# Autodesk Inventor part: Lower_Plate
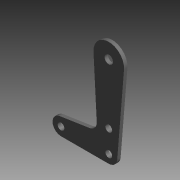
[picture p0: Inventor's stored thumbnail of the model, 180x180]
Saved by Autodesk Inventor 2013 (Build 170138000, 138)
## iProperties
Shininess: 15.0
Length Units: 11272
Angle Units: 11279
Time Units: 11290
Mass Units: 11283
Length Display Precision: 2
Angle Display Precision: 1
Compacted: True
Created: 1999-05
Part Number: Lower_Plate
Document SubType Name: Modeling
Designer: Administrator
Density: 8.83 g/cm^3
Material: NICU, Monel 400
Density: 8.83
Volumn: 8.899101648082546
Area: 68.18129680210748
PropertySet Name: Model Information
Control State: 0
Master: False
Checked Out: False
Author: Administrator
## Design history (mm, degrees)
node "y-z Plane"
  node "x-z Plane"
  node "x-y Plane"
node "Extrusion1" dims "d6" = 3.175, "d7" = 0
  sketch "Sketch1"
    geometry: L1 (-44.45, -84.074)-(0, -84.074); L2 (7.847, -76.856)-(14.175, -1.185); L3 (-14.203, -0.776)-(-11.188, -55.993); L4 (-17.87, -64.207)-(-45.63, -68.415); L5 (0, 0)-(0, -76.2); A1 r 7.874 centre (0, -76.2) between (0, -84.074) and (7.847, -76.856); A2 r 14.224 centre (0, 0) between (14.175, -1.185) and (-14.203, -0.776); A3 r 7.874 centre (-19.05, -56.422) between (-17.87, -64.207) and (-11.188, -55.993); A4 r 7.874 centre (-44.45, -76.2) between (-45.63, -68.415) and (-44.45, -84.074); 1 further point
    constraints: 10 end point, 8 point on circle, 8 tangent, 4 centre point, 1 coincident, 1 horizontal, 1 horizontal alignment, 1 perpendicular, 1 vertical alignment
    dimensions: "d0" = 76.2 distance of L5.end L5.start; "d1" = 44.45 distance of A4.centre L5.end; "d2" = 14.224 radius of A2; "d3" = 7.874 radius of A3; "d4" = 7.874 radius of A4; "d5" = 19.05 horizontal distance of A3.centre L5.end; "d23" = 56.42223 vertical distance of A3.centre L5.start
node "Hole1" dims "d9" = 6.35, "d10" = 9.525, "d11" = 6.35, "d12" = 60 deg, "d13" = 19.05, "d14" = 118 deg
  sketch "Sketch2"
    geometry: A1 r 7.874 centre (0, -76.2) between (0, -84.074) and (7.847, -76.856) reference; A2 r 7.874 centre (-44.45, -76.2) between (-45.63, -68.415) and (-44.45, -84.074) reference; 1 further point
    dimensions: "d8" = 20.574 distance of point (0, -55.626) A1.centre
node "Hole2" dims "d15" = 7.874, "d16" = 9.525, "d17" = 6.35, "d18" = 60 deg, "d19" = 19.05, "d20" = 118 deg
  sketch "Sketch3"
    geometry: A1 r 14.224 centre (0, 0) between (14.175, -1.185) and (-14.203, -0.776) reference
body "Solid1"
